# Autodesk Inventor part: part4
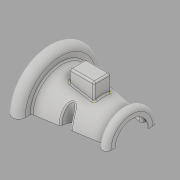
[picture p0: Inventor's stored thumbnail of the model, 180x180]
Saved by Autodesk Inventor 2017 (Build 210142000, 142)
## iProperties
Created: 2015-05
Part Number: part4
Material: Generic
Document SubType Name: Modeling
Designer: Sandeep
Density: 1 g/cm^3
Appearance: Default
Author: Sandeep
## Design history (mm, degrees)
sketch "Sketch1"
  geometry: L1 (-36.486, 0)-(29.175, 0) reference; L2 (-50, 30)-(-50, 42.5); L3 (-35, 42.5)-(-35, 35); L4 (-35, 35)-(40, 22.5); L5 (40, 22.5)-(40, 25); L6 (50, 25)-(50, 20); A1 r 7.5 centre (-42.5, 42.5) between (-35, 42.5) and (-50, 42.5); A2 r 5 centre (45, 25) between (50, 25) and (40, 25); 1 further point
  constraints: 12 end point, 4 point on circle, 4 tangent, 3 parallel, 2 centre point, 2 horizontal, 1 point on line, 1 vertical
  dimensions: "d1" = 50 distance from line of point (0, 0) L2; "d2" = 100 distance between parallel lines of L2 L6; "d3" = 5 radius of A2; "d4" = 7.5 radius of A1; "d5" = 85 diameter of L2.end L1; "d6" = 60 diameter of L2.start L1; "d7" = 70 diameter of L3.end L1; "d9" = 50 diameter of L6.start L1; "d10" = 45 diameter of L4.end L1; "d11" = 40 diameter of L6.end L1
feature "RevolutionSrf1" sketch "Sketch1" dims angle "d12" = 180 deg
sketch "Sketch2" dims "d14" = 10, "d15" = 5
  geometry: L1 (-35, 35)-(40, 22.5) reference; L2 (50, -25)-(50, 25) reference; 2 further points; 1 other entity
  constraints: 1 point on line, 2 other
  dimensions: "d13" = 50 distance from line of L2 point (0, 29.167)
extrude_surface "ExtrusionSrf1" sketch "Sketch2" dims "d16" = 30, "d17" = 0
mirror "Mirror1"
feature "Trim1"
feature "Trim2"
feature "Trim3"
feature "Trim4"
workplane "Work Plane1"
sketch "Sketch3"
  geometry: L1 (-15, 10)-(15, 10); L2 (15, 10)-(15, -10); L3 (15, -10)-(-15, -10); L4 (-15, -10)-(-15, 10); L5 (0, 19.961)-(0, 0); L6 (0, 0)-(-34.336, 0)
  constraints: 12 end point, 2 horizontal, 2 parallel, 1 perpendicular, 1 vertical, 2 other
  dimensions: "d19" = 30 distance between parallel lines of L2 L4; "d20" = 20 distance of L1.end L2.end
split "Split1"
delete_face "Delete Face1"
sketch "3D Sketch1"
  geometry: L1 through (0, 0) direction (1, 0) reference; L2 through (0, 0) direction (-1, 0) reference; 4 other entities
  constraints: 6 horizontal
feature "Stitch Surface1"
fillet "Fillet1" dims "d25" = 2
feature "Stitch Surface3"
thicken "Thicken1" dims "d28" = 1
fillet "Fillet4" dims "d29" = 2
fillet "Fillet5" dims "d30" = 2
fillet "Fillet6" dims "d31" = 2
body "Solid1"
body "Srf1"
body "Srf2"
body "Srf3"
node "Edges1"
body "Srf4"
body "Srf5"
body "Srf6"
body "Srf8"
extrude_surface "ExtrusionSrf2"
feature "LoftSrf1" dims "d21" = 0, "d22" = 90 deg, "d23" = 0, "d24" = 90 deg
patch "Boundary Patch1"
other parameters: "d18" = 45
